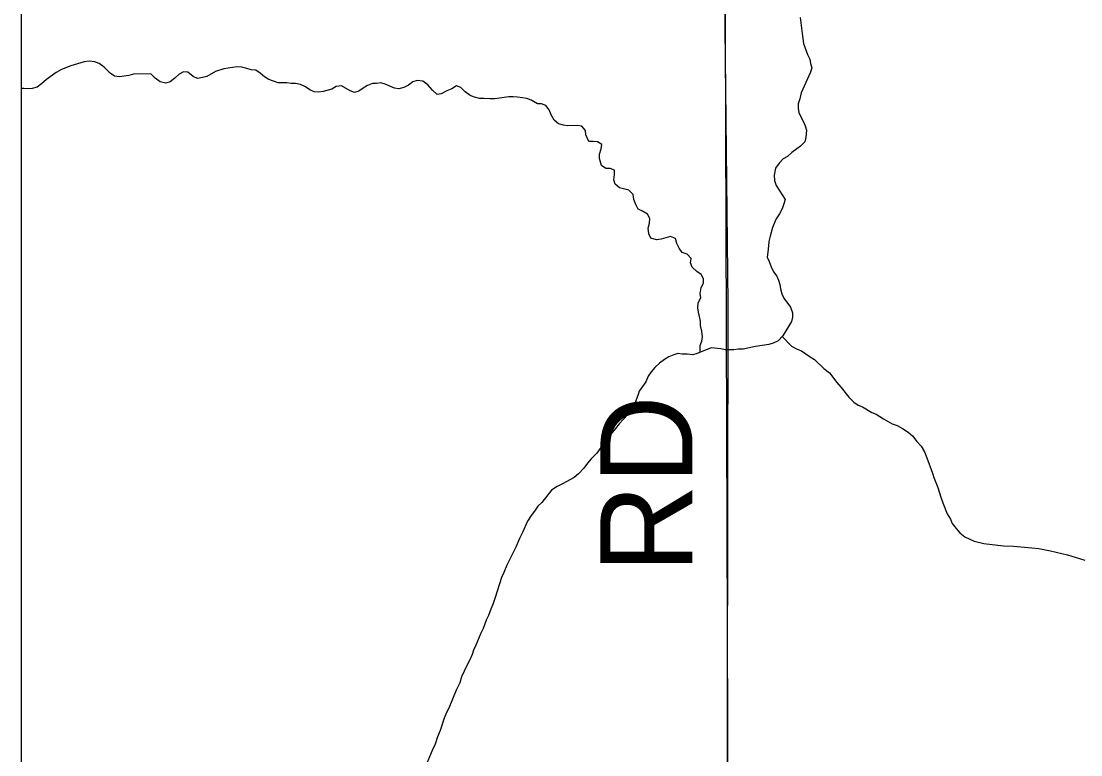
# Model space of a CAD drawing. Extents: x 0 to 34, y 0 to 22.
# Drawn here: x 2.1 to 2.754, y 16.272 to 16.725 of the extents above; entities that cross this region are included whole.
import ezdxf

# ---------------------------------------------------------------- set-up
doc = ezdxf.new("R2010")
doc.units = 0
for name, color, linetype in [('GM_X_Minor_River', 7, 'Continuous'), ('GM_X_Rail_Line', 7, 'Continuous'), ('GM_X_Section', 7, 'Continuous'), ('GM_X_Township_Road', 7, 'Continuous'), ('GM_X_Township_Road_Text', 7, 'Continuous'), ('SH_Cut_Line', 7, 'Continuous'), ('SH_Data', 7, 'Continuous')]:
    doc.layers.add(name, color=color, linetype=linetype)

msp = doc.modelspace()

# ---------------------------------------------------------------- linework, layer by layer
at = {"layer": 'GM_X_Minor_River'}
for points in [[(2.58048, 16.72688), (2.58173, 16.71701), (2.58256, 16.71094), (2.58491, 16.70413), (2.58647, 16.70111), (2.58687, 16.69845), (2.58766, 16.6958), (2.58694, 16.69313), (2.58101, 16.68052), (2.5803, 16.67671), (2.57919, 16.67366), (2.57922, 16.671), (2.57963, 16.66835), (2.5808, 16.6657), (2.58235, 16.66306), (2.58352, 16.66003), (2.58431, 16.65738), (2.58398, 16.65282), (2.58326, 16.65015), (2.58063, 16.64746), (2.57537, 16.64359), (2.57274, 16.64128), (2.5701, 16.63973), (2.56748, 16.63704), (2.56523, 16.63397), (2.56452, 16.62978), (2.56456, 16.62636), (2.56574, 16.62334), (2.57115, 16.61466), (2.57042, 16.61199), (2.56932, 16.60894), (2.56783, 16.60588), (2.56559, 16.60281), (2.56338, 16.59747), (2.56192, 16.59213), (2.5612, 16.5887), (2.56085, 16.58604), (2.56052, 16.58223), (2.56017, 16.57919), (2.56134, 16.57654)], [(2.31659, 16.68611), (2.31357, 16.68493), (2.31093, 16.68338), (2.3083, 16.68145), (2.30565, 16.68066), (2.30298, 16.68177), (2.29764, 16.68474), (2.29423, 16.68432), (2.29159, 16.68277), (2.2863, 16.68119), (2.28327, 16.68077), (2.28061, 16.68112), (2.27795, 16.68223), (2.27527, 16.6841), (2.27222, 16.68558), (2.26917, 16.6863), (2.26652, 16.68627), (2.26386, 16.68662), (2.25855, 16.68656), (2.25284, 16.68877), (2.25016, 16.69025), (2.24748, 16.6925), (2.24481, 16.69437), (2.24177, 16.69472), (2.23911, 16.69544), (2.23606, 16.69617), (2.23302, 16.69651), (2.22507, 16.69528), (2.21978, 16.69369), (2.21451, 16.69059), (2.21186, 16.6898), (2.20883, 16.68938), (2.20617, 16.69049), (2.20272, 16.69311), (2.20006, 16.69346), (2.19743, 16.69191), (2.1948, 16.68959), (2.19179, 16.68728), (2.18914, 16.68649), (2.18572, 16.68721), (2.18266, 16.68945), (2.17998, 16.69208), (2.16936, 16.69195), (2.16633, 16.69115), (2.16065, 16.69032), (2.15761, 16.69067), (2.15494, 16.69254), (2.1511, 16.69629), (2.14804, 16.69853), (2.14537, 16.69964), (2.14196, 16.69998), (2.13893, 16.69957), (2.13061, 16.69719), (2.12495, 16.69484), (2.12156, 16.6929), (2.11554, 16.68864), (2.11253, 16.68595), (2.1099, 16.68402), (2.10687, 16.68322), (2.10422, 16.68281), (2.10157, 16.68316), (2.1, 16.68314)], [(2.51888, 16.52059), (2.5187, 16.52473), (2.5198, 16.5274), (2.52015, 16.53007), (2.51973, 16.53348), (2.51894, 16.5369), (2.51891, 16.53956), (2.51849, 16.54259), (2.5177, 16.54524), (2.51729, 16.5479), (2.51764, 16.55094), (2.51912, 16.554), (2.51871, 16.55665), (2.51943, 16.56046), (2.52091, 16.56314), (2.52088, 16.5658), (2.51934, 16.56844), (2.51666, 16.57031), (2.51397, 16.57294), (2.5128, 16.57558), (2.51315, 16.57825), (2.51085, 16.58088), (2.5078, 16.58199), (2.50587, 16.58462), (2.50432, 16.58764), (2.50353, 16.59067), (2.50048, 16.59178), (2.49481, 16.59019), (2.49178, 16.58977), (2.48836, 16.59087), (2.48719, 16.59352), (2.48677, 16.59693), (2.48749, 16.59998), (2.48784, 16.60303), (2.48629, 16.60567), (2.48323, 16.60753), (2.48057, 16.60864), (2.47902, 16.61166), (2.47784, 16.61469), (2.47743, 16.61772), (2.47474, 16.62035), (2.46904, 16.62181), (2.46636, 16.62405), (2.46557, 16.6267), (2.46591, 16.63013), (2.46588, 16.63279), (2.46321, 16.63389), (2.46055, 16.63386), (2.45788, 16.63573), (2.4567, 16.6399), (2.45666, 16.64256), (2.45776, 16.64599), (2.45811, 16.64866), (2.45544, 16.65014), (2.45278, 16.65049), (2.45012, 16.65046), (2.44818, 16.65462), (2.44815, 16.65728), (2.44584, 16.65991), (2.44319, 16.66026), (2.43712, 16.66019), (2.43446, 16.66053), (2.43142, 16.66126), (2.42873, 16.66351), (2.4268, 16.6669), (2.42563, 16.66993), (2.4237, 16.67257), (2.42103, 16.67368), (2.41838, 16.67364), (2.41456, 16.67588), (2.41189, 16.67699), (2.40923, 16.67733), (2.4062, 16.67768), (2.40354, 16.67803), (2.40088, 16.678), (2.39217, 16.67675), (2.38914, 16.67671), (2.38534, 16.67705), (2.38269, 16.67702), (2.37965, 16.67774), (2.37698, 16.67885), (2.37392, 16.68109), (2.37123, 16.68372), (2.36856, 16.68483), (2.36555, 16.68289), (2.36253, 16.68172), (2.35914, 16.67978), (2.35649, 16.67936), (2.3538, 16.68199), (2.35073, 16.68538), (2.34767, 16.68762), (2.34425, 16.68796), (2.34161, 16.68717), (2.33898, 16.68524), (2.33596, 16.68368), (2.33293, 16.68289), (2.33027, 16.68323), (2.32455, 16.68582), (2.32189, 16.68655), (2.31924, 16.68614), (2.31659, 16.68611)], [(2.56134, 16.57654), (2.56252, 16.57314), (2.56407, 16.57011), (2.566, 16.56748), (2.56716, 16.56483), (2.56795, 16.56218), (2.56837, 16.55953), (2.56916, 16.5565), (2.57033, 16.55385), (2.57456, 16.5482), (2.57574, 16.54479), (2.57577, 16.54213), (2.57504, 16.53946), (2.56983, 16.53066), (2.56684, 16.52759), (2.56382, 16.52603), (2.56117, 16.52524), (2.55284, 16.524), (2.54527, 16.52239), (2.54224, 16.52235), (2.53959, 16.52194), (2.53694, 16.52191), (2.53428, 16.52188), (2.53162, 16.5226), (2.52554, 16.52329), (2.51686, 16.51977), (2.51421, 16.51898), (2.5108, 16.51932), (2.50776, 16.51928), (2.5051, 16.51963), (2.50246, 16.51884), (2.49944, 16.51766), (2.4968, 16.51611), (2.49379, 16.51379), (2.49079, 16.5111), (2.48854, 16.50841), (2.48668, 16.50573), (2.4852, 16.50229), (2.48109, 16.49654), (2.48036, 16.49387), (2.47816, 16.48777), (2.47667, 16.48509), (2.47443, 16.4824), (2.47143, 16.47932), (2.46881, 16.47625), (2.46582, 16.47242), (2.46245, 16.46858), (2.46021, 16.46513), (2.4576, 16.46168), (2.45498, 16.45823), (2.45161, 16.45477), (2.44936, 16.45208), (2.44712, 16.44902), (2.44375, 16.44555), (2.44112, 16.44324), (2.43396, 16.43936), (2.43056, 16.4378), (2.42717, 16.43548), (2.4212, 16.4278), (2.41857, 16.42549), (2.4167, 16.42243), (2.41446, 16.41974), (2.41223, 16.4163), (2.40927, 16.40942), (2.40741, 16.4056), (2.4052, 16.40025), (2.39964, 16.38917), (2.39779, 16.38458), (2.39631, 16.38153), (2.39228, 16.36932), (2.39119, 16.3655), (2.38971, 16.36207), (2.38823, 16.35825), (2.38675, 16.35519), (2.38491, 16.35023), (2.38343, 16.34717), (2.38048, 16.33991), (2.379, 16.33686), (2.37827, 16.33419), (2.37679, 16.33075), (2.37494, 16.32731), (2.3716, 16.32043), (2.37051, 16.31661), (2.36828, 16.31203), (2.36386, 16.30095), (2.36237, 16.29828), (2.36089, 16.29484), (2.35833, 16.28721), (2.35685, 16.28339), (2.35539, 16.27881), (2.35354, 16.27499), (2.3491, 16.26468)], [(2.56946, 16.53028), (2.57522, 16.52426), (2.57865, 16.52241), (2.58132, 16.5213), (2.58667, 16.51756), (2.58934, 16.51607), (2.5951, 16.51044), (2.59854, 16.50782), (2.60316, 16.5018), (2.60585, 16.49879), (2.61047, 16.49276), (2.61354, 16.48976), (2.61622, 16.48789), (2.61888, 16.48678), (2.62461, 16.48343), (2.62728, 16.48232), (2.63186, 16.47934), (2.63721, 16.47636), (2.64026, 16.47526), (2.64369, 16.4734), (2.64713, 16.47116), (2.64981, 16.46891), (2.6525, 16.46552), (2.65519, 16.46251), (2.65713, 16.45912), (2.65869, 16.45534), (2.66221, 16.44588), (2.663, 16.44323), (2.66534, 16.43717), (2.66731, 16.43112), (2.66849, 16.42771), (2.67122, 16.4209), (2.67315, 16.41751), (2.67432, 16.41486), (2.67663, 16.41185), (2.67894, 16.40921), (2.682, 16.40659), (2.68772, 16.404), (2.69381, 16.40255), (2.70596, 16.40118), (2.71203, 16.40087), (2.72342, 16.39986), (2.7276, 16.39953), (2.73482, 16.3981), (2.74547, 16.39557), (2.75613, 16.39227)]]:
    msp.add_lwpolyline(points, dxfattribs=at)
at = {"layer": 'GM_X_Rail_Line'}
msp.add_lwpolyline([(2.1, 17.21074), (2.1, 14.1), (5.56188, 14.1), (5.56081, 14.20501), (5.56145, 14.24143), (5.55954, 14.64394), (5.55832, 14.93466), (5.55813, 14.96763), (5.55884, 15.17468), (5.55786, 15.2049), (4.08475, 15.1965), (3.54112, 15.19308), (3.5298, 15.93177), (3.52691, 16.35494), (3.51103, 17.2267), (3.47106, 17.22616), (2.94944, 17.22031), (2.52179, 17.21551)], close=True, dxfattribs=at)
at = {"layer": 'GM_X_Section'}
msp.add_lwpolyline([(3.52446, 17.2236), (3.5333, 16.18652), (2.53623, 16.1651), (2.53288, 17.21377), (3.47292, 17.22309)], close=True, dxfattribs=at)
at = {"layer": 'GM_X_Township_Road'}
msp.add_lwpolyline([(2.53903, 15.92957), (2.53701, 16.03125), (2.53548, 16.17799), (2.53617, 16.55063), (2.5321, 16.909), (2.52199, 17.21496)], dxfattribs=at)
at = {"layer": 'SH_Cut_Line'}
msp.add_lwpolyline([(2.94944, 17.22031), (2.52179, 17.21551), (2.1, 17.21074), (2.1, 14.1)], dxfattribs=at)
at = {"layer": 'SH_Data'}
msp.add_line((2.1, 20.9), (2.1, 14.1), dxfattribs=at)

# ---------------------------------------------------------------- texts
at = {"layer": 'GM_X_Township_Road_Text'}
msp.add_text('RD', height=0.056818, rotation=90, dxfattribs=at).set_placement((2.51405, 16.38421))

doc.saveas('drawing.dxf')
